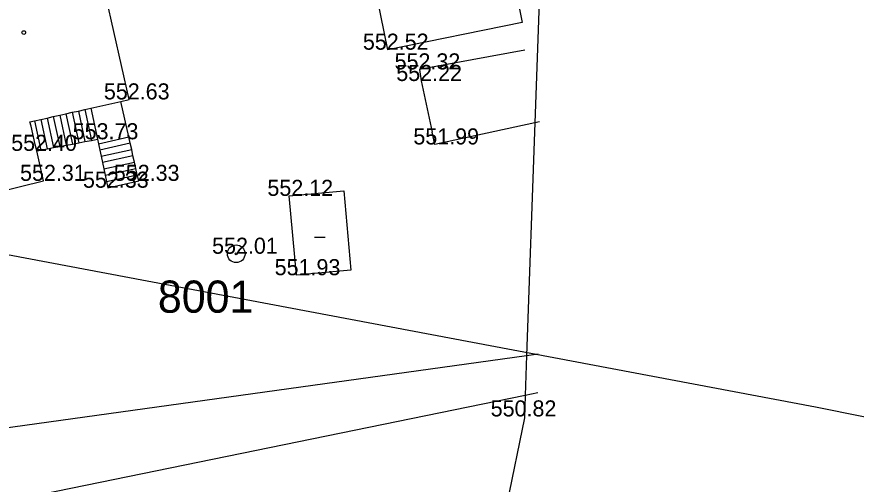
# Model space of a CAD drawing. Extents: x -669393 to -668650, y -1126925 to -1126294.
# Drawn here: x -669019.8 to -668980.61, y -1126529.65 to -1126507.85 of the extents above; entities that cross this region are included whole.
import ezdxf

# ---------------------------------------------------------------- set-up
doc = ezdxf.new("R2010")
doc.units = 0
for name, color, linetype in [('G_Bod_tecka', 7, 'Continuous'), ('G_Bod_vyska', 7, 'Continuous'), ('G_Bodove_pole', 7, 'Continuous'), ('G_Breh_Teren', 7, 'Continuous'), ('G_Budovy-znacky', 7, 'Continuous'), ('G_Budovy_Objekty', 7, 'Continuous'), ('G_Budovy_vstupy', 7, 'Continuous'), ('G_Cesty_Schody', 7, 'Continuous'), ('G_Ploty', 7, 'Continuous'), ('G_Z_ELsilove_nadz_kotovane', 7, 'Continuous')]:
    doc.layers.add(name, color=color, linetype=linetype)

msp = doc.modelspace()

# ---------------------------------------------------------------- linework, layer by layer
at = {"layer": 'G_Bod_tecka'}
for p, q in [((-669002.48, -1126509.38), (-669002.48, -1126509.38)), ((-669001, -1126510.3), (-669001, -1126510.3)), ((-669000.93, -1126510.84), (-669000.93, -1126510.84)), ((-669014.56, -1126511.7), (-669014.56, -1126511.7)), ((-669016.03, -1126513.56), (-669016.03, -1126513.56)), ((-669000.26, -1126513.8), (-669000.26, -1126513.8)), ((-669018.88, -1126514.1), (-669018.88, -1126514.1)), ((-669018.55, -1126515.5), (-669018.55, -1126515.5)), ((-669014.11, -1126515.5), (-669014.11, -1126515.5)), ((-669015.55, -1126515.82), (-669015.55, -1126515.82)), ((-669007.08, -1126516.2), (-669007.08, -1126516.2)), ((-669009.56, -1126518.9), (-669009.56, -1126518.9)), ((-669006.74, -1126519.9), (-669006.74, -1126519.9)), ((-668996.49, -1126526.49), (-668996.49, -1126526.49))]:
    msp.add_line(p, q, dxfattribs=at)
at = {"layer": 'G_Bodove_pole'}
for radius in [0.412, 0.05]:
    msp.add_circle((-669009.56, -1126518.9), radius, dxfattribs=at)
at = {"layer": 'G_Breh_Teren'}
for points in [[(-668996, -1126523.64), (-668995.46, -1126523.57)], [(-669031.1, -1126528.51), (-668996, -1126523.64)], [(-668996.06, -1126525.51), (-669030.52, -1126532.56)], [(-668995.48, -1126525.39), (-668996.06, -1126525.51)]]:
    msp.add_lwpolyline(points, dxfattribs=at)
at = {"layer": 'G_Budovy-znacky'}
msp.add_line((-669005.9, -1126518.13), (-669005.4, -1126518.13), dxfattribs=at)
msp.add_circle((-669019.48, -1126508.58), 0.0875, dxfattribs=at)
at = {"layer": 'G_Budovy_Objekty'}
for p, q in [((-668997.21, -1126503.16), (-668996.21, -1126508.11)), ((-669014.56, -1126511.7), (-669016.34, -1126503.82)), ((-669002.48, -1126509.38), (-669003.48, -1126504.43)), ((-668996.21, -1126508.11), (-669002.48, -1126509.38)), ((-668996.08, -1126509.4), (-669001, -1126510.3)), ((-669001, -1126510.3), (-669000.93, -1126510.84)), ((-669016.34, -1126512.1), (-669014.95, -1126511.79)), ((-669014.95, -1126511.79), (-669014.56, -1126511.7)), ((-669017.22, -1126512.3), (-669016.93, -1126512.24)), ((-669016.93, -1126512.24), (-669016.63, -1126512.17)), ((-669016.63, -1126512.17), (-669016.34, -1126512.1)), ((-669018.97, -1126512.7), (-669018.68, -1126512.64)), ((-669018.68, -1126512.64), (-669018.39, -1126512.57)), ((-669018.39, -1126512.57), (-669018.1, -1126512.5)), ((-669018.1, -1126512.5), (-669017.8, -1126512.44)), ((-669017.8, -1126512.44), (-669017.51, -1126512.37)), ((-669017.51, -1126512.37), (-669017.22, -1126512.3)), ((-669019.19, -1126512.75), (-669018.97, -1126512.7)), ((-669019.14, -1126512.95), (-669019.19, -1126512.75)), ((-668995.61, -1126512.79), (-669000.28, -1126513.81)), ((-668995.4, -1126512.75), (-668995.61, -1126512.79)), ((-669000.28, -1126513.81), (-669000.41, -1126513.22)), ((-669018.87, -1126514.1), (-669018.95, -1126513.8)), ((-669018.55, -1126515.5), (-669018.87, -1126514.1)), ((-669022.54, -1126516.46), (-669018.55, -1126515.5)), ((-669007.08, -1126516.2), (-669004.54, -1126515.97)), ((-669004.54, -1126515.97), (-669004.2, -1126519.67)), ((-669006.74, -1126519.9), (-669007.08, -1126516.2)), ((-669004.2, -1126519.67), (-669006.74, -1126519.9))]:
    msp.add_line(p, q, dxfattribs=at)
at = {"layer": 'G_Budovy_vstupy'}
for p, q in [((-669000.93, -1126510.84), (-669000.41, -1126513.22)), ((-669018.95, -1126513.8), (-669019.14, -1126512.95))]:
    msp.add_line(p, q, dxfattribs=at)
at = {"layer": 'G_Cesty_Schody'}
for p, q in [((-669014.58, -1126513.45), (-669014.95, -1126511.79)), ((-669016.93, -1126512.24), (-669016.62, -1126513.67)), ((-669016.63, -1126512.17), (-669016.32, -1126513.62)), ((-669016.34, -1126512.1), (-669016.03, -1126513.56)), ((-669018.68, -1126512.64), (-669018.39, -1126514.01)), ((-669018.39, -1126512.57), (-669018.09, -1126513.95)), ((-669018.1, -1126512.5), (-669017.8, -1126513.9)), ((-669017.8, -1126512.44), (-669017.5, -1126513.84)), ((-669017.51, -1126512.37), (-669017.21, -1126513.78)), ((-669017.22, -1126512.3), (-669016.91, -1126513.73)), ((-669018.97, -1126512.7), (-669018.68, -1126514.06)), ((-669017.5, -1126513.84), (-669017.21, -1126513.78)), ((-669017.21, -1126513.78), (-669016.91, -1126513.73)), ((-669016.91, -1126513.73), (-669016.62, -1126513.67)), ((-669016.62, -1126513.67), (-669016.32, -1126513.62)), ((-669016.32, -1126513.62), (-669016.03, -1126513.56)), ((-669016.03, -1126513.56), (-669015.99, -1126513.77)), ((-669015.99, -1126513.77), (-669014.58, -1126513.45)), ((-669015.99, -1126513.77), (-669015.92, -1126514.06)), ((-669014.51, -1126513.74), (-669015.92, -1126514.06)), ((-669014.51, -1126513.74), (-669014.58, -1126513.45)), ((-669014.44, -1126514.04), (-669014.51, -1126513.74)), ((-669018.87, -1126514.1), (-669018.68, -1126514.06)), ((-669018.68, -1126514.06), (-669018.39, -1126514.01)), ((-669018.39, -1126514.01), (-669018.09, -1126513.95)), ((-669018.09, -1126513.95), (-669017.8, -1126513.9)), ((-669017.8, -1126513.9), (-669017.5, -1126513.84)), ((-669015.92, -1126514.06), (-669015.86, -1126514.35)), ((-669015.86, -1126514.35), (-669014.44, -1126514.04)), ((-669014.38, -1126514.33), (-669014.44, -1126514.04)), ((-669015.86, -1126514.35), (-669015.8, -1126514.65)), ((-669014.38, -1126514.33), (-669015.8, -1126514.65)), ((-669014.31, -1126514.62), (-669014.38, -1126514.33)), ((-669015.8, -1126514.65), (-669015.74, -1126514.94)), ((-669015.74, -1126514.94), (-669014.31, -1126514.62)), ((-669015.74, -1126514.94), (-669015.68, -1126515.23)), ((-669015.68, -1126515.23), (-669014.24, -1126514.92)), ((-669014.24, -1126514.92), (-669014.31, -1126514.62)), ((-669014.18, -1126515.21), (-669014.24, -1126514.92)), ((-669015.68, -1126515.23), (-669015.61, -1126515.53)), ((-669015.61, -1126515.53), (-669014.18, -1126515.21)), ((-669014.11, -1126515.5), (-669014.18, -1126515.21)), ((-669015.61, -1126515.53), (-669015.55, -1126515.82)), ((-669015.55, -1126515.82), (-669014.11, -1126515.5))]:
    msp.add_line(p, q, dxfattribs=at)
at = {"layer": 'G_Ploty'}
for p, q in [((-668995.61, -1126512.79), (-668996, -1126523.64)), ((-668996, -1126523.64), (-668996.06, -1126525.51)), ((-668996.06, -1126525.51), (-668996.1, -1126526.56)), ((-668996.1, -1126526.56), (-669002.57, -1126558.11))]:
    msp.add_line(p, q, dxfattribs=at)
msp.add_lwpolyline([(-668998.62, -1126489.45), (-668995.25, -1126502.77), (-668995.61, -1126512.79)], dxfattribs=at)
at = {"layer": 'G_Z_ELsilove_nadz_kotovane'}
msp.add_lwpolyline([(-668947.579, -1126533.09), (-668982.508, -1126526.058), (-669027.842, -1126517.524), (-669063.798, -1126525.039), (-669116.134, -1126538.61), (-669151.93, -1126546.06), (-669151.59, -1126545.64)], dxfattribs=at)

# ---------------------------------------------------------------- texts
at = {"layer": 'G_Bod_vyska'}
for s, p in [('552.52', (-669003.644, -1126509.38)), ('552.32', (-669002.164, -1126510.3)), ('552.22', (-669002.084, -1126510.84)), ('552.63', (-669015.738, -1126511.7)), ('553.73', (-669017.194, -1126513.56)), ('551.99', (-669001.286, -1126513.8)), ('552.40', (-669020.066, -1126514.1)), ('552.31', (-669019.652, -1126515.5)), ('552.33', (-669015.274, -1126515.5)), ('552.33', (-669016.714, -1126515.82)), ('552.12', (-669008.102, -1126516.2)), ('552.01', (-669010.684, -1126518.9)), ('551.93', (-669007.764, -1126519.9)), ('550.82', (-668997.676, -1126526.49))]:
    msp.add_text(s, height=0.75, dxfattribs=at).set_placement(p)
at = {"layer": 'G_Bodove_pole'}
msp.add_text('8001', height=1.5, dxfattribs=at).set_placement((-669013.217, -1126521.65))

doc.saveas('drawing.dxf')
